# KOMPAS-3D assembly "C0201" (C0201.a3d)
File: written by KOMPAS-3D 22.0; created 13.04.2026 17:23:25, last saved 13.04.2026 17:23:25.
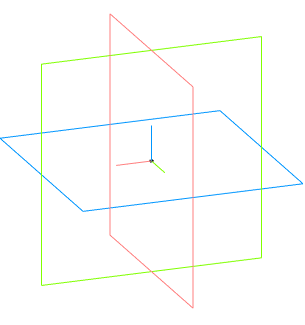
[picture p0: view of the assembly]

Document properties: Автор: Andrey; Полное имя файла: C:\Users\User1\Documents\C0201.a3d

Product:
- Component [detail]: GRM_Auto_Q3_0.6_0.3_0.33_0.15  | qty 1  | source file: GRM_Auto_Q3_0.6_0.3_0.33_0.15.m3d
- Part/product: C0201
    Комментарий: C0201

Referenced files in C:\Users\User1\Documents\: GRM_Auto_Q3_0.6_0.3_0.33_0.15.m3d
